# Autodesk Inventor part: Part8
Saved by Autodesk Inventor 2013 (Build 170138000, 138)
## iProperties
Created: 2012-07
Part Number: Part8
Material: Generic
Document SubType Name: Modeling
Designer: Paul
Density: 1 g/cm^3
Author: Paul
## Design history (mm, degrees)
node "User Library-Arduino Mega.SAT1"
body "Solid1"
node "Base1"
